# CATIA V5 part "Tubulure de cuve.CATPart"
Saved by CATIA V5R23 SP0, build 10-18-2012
Part number: Tubulure de cuve
Publications: "CATRouHole1", "CATRouCenter1", "CATRouCircular1", "CATRouDatumPt1"
Bounding box of the stored display mesh (mm): x -499.988 to 499.994, y -500 to 600, z 0 to 973
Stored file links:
  C:\Users\bordron1\Downloads\Tubulure de cuve.CATPart
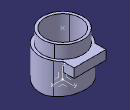
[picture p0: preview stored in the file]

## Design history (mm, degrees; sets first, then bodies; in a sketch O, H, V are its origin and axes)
AxisSystem1: origin (0, 0, 0), X (1, 0, 0), Y (0, 1, 0), Z (0, 0, 1)
Set1
  Plane1: type Offset, RefPlane ZX plane of AxisSystem1, Offset 600
  Point1: type Center, Curve edge [face of Shaft1 from Sketch1.L3 | face of Shaft1 from Sketch1.L2]
Body1 (main body)
  Sketch1 on ZX plane of AxisSystem1, origin (0, 0, 0), H (0, 0, 1), V (1, 0, 0)
    line L1 (0, -500) -> (693, -500)
    point P1 (0, -500)
    line L2 (0, -385) -> (973, -385)
    point P3 (0, -385)
    line L3 (973, -385) -> (973, -442.5)
    line L4 (973, -442.5) -> (693, -442.5)
    line L5 (693, -442.5) -> (693, -500)
    reference projected line E1 through (0, 0) direction (1, 0) from edge [ZX plane of AxisSystem1 | YZ plane of AxisSystem1]
    reference projected line E2 through (0, 0) direction (1, 0) from edge [ZX plane of AxisSystem1 | YZ plane of AxisSystem1]
    line L6 (0, -385) -> (0, -500)
    distance E1 L2 = 385
    length L2 = 973
    length L4 = 280
    distance L1 E2 = 500
    coincidence: P1 V, P3 V
    horizontal: L1 H, L2 H, L4 H
    vertical: L3 V, L5 V, L6 V
    symmetry: L1 L2 L4
  Shaft1: profile Sketch1, axis edge [ZX plane of AxisSystem1 | YZ plane of AxisSystem1], angle 360
  Sketch2 on Plane1, origin (0, 600, 0), H (0, 0, 1), V (1, 0, 0)
    line L1 (493, 350) -> (693, 350)
    line L2 (693, 350) -> (693, -350)
    line L3 (693, -350) -> (493, -350)
    line L4 (493, -350) -> (493, 350)
    reference intersected line E1 through (0, 0) direction (-1, 0) from YZ plane of AxisSystem1
    reference projected line E2 (693, 500) -> (693, -500) from edge [face of Shaft1 from Sketch1.L1 | face of Shaft1 from Sketch1.L5]
    length L3 = 200
    distance L3 L1 = 700
    horizontal: L1 H, L3 H
    vertical: L2 V, L4 V
    symmetry: L3 L1 E1
    coincidence: L2 E2
  Pad1: profile Sketch2, direction (0, 1, 0), up to the existing solid (limit type 2)
  Sketch3 on ZX plane of AxisSystem1, origin (0, 0, 0), H (0, 0, 1), V (1, 0, 0)
    circle A1 centre (-2078, 0) radius 2140
    point P1 (-2078, 0)
    radius A1 = 2140
    distance A1 V = 62
    coincidence: P1 H
  Pocket1: profile Sketch3, direction (0, -1, 0), length 550, mirrored extent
